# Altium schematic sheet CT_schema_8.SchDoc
size 278 x 170 mm
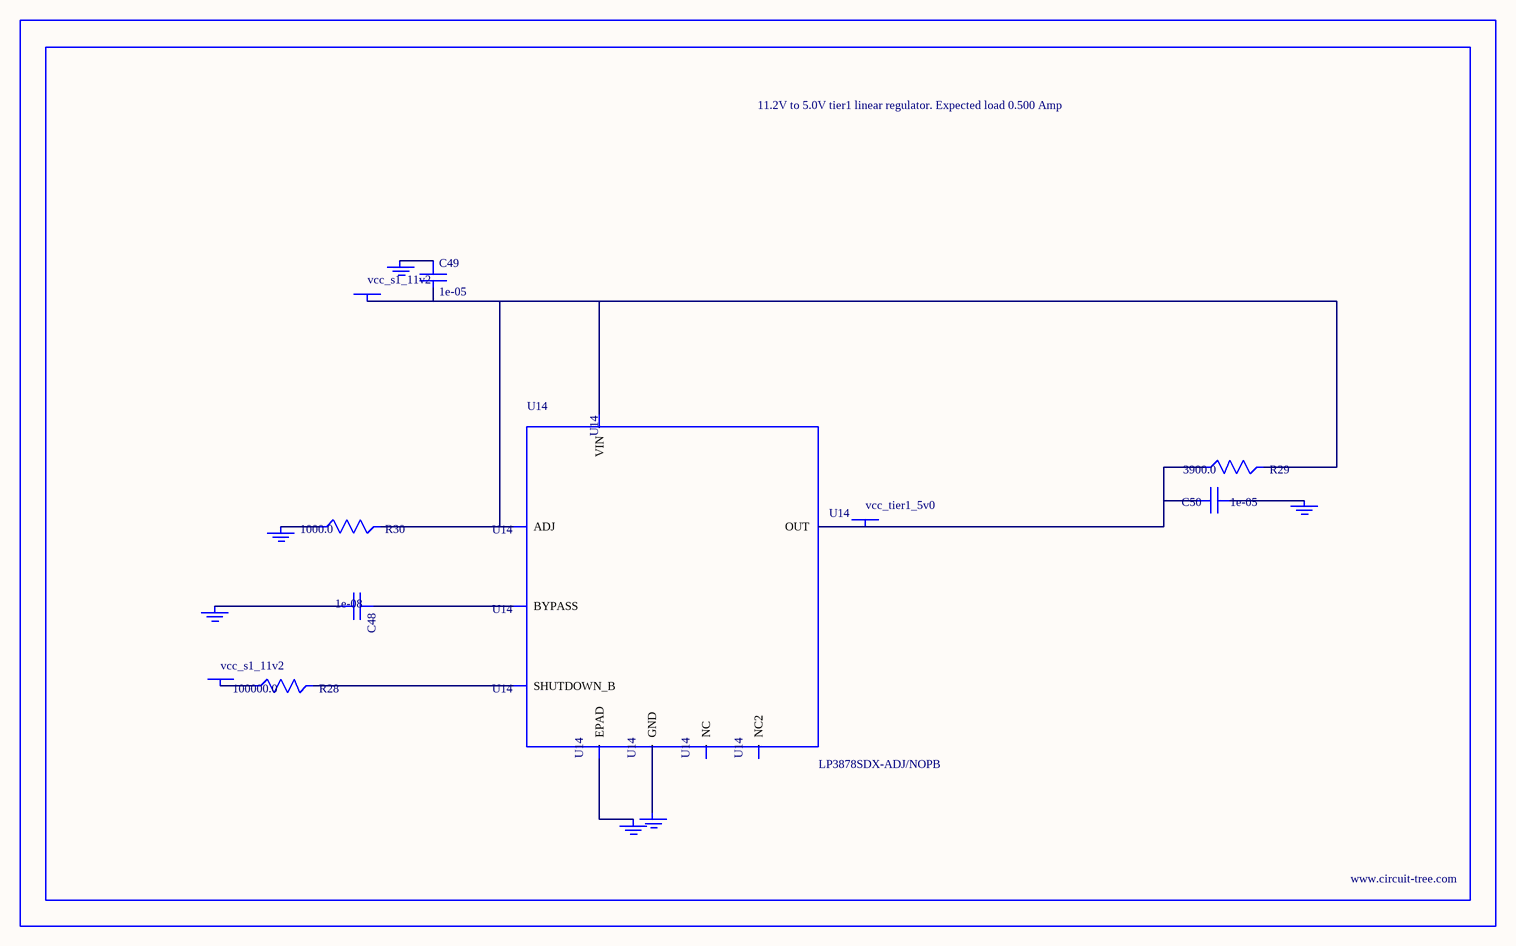
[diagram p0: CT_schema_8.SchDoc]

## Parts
BORDER7  (no value)
C48  1e-08  [C0402]
C49  1e-05  [C1210]
C50  1e-05  [C1210]
GND_INSTANCE_7_0  (no value)
GND_INSTANCE_7_1  (no value)
GND_INSTANCE_7_2  (no value)
GND_INSTANCE_7_3  (no value)
GND_INSTANCE_7_4  (no value)
GND_INSTANCE_7_5  (no value)
POWER_INSTANCE_7_0  vcc_s1_11v2
POWER_INSTANCE_7_1  vcc_s1_11v2
POWER_INSTANCE_7_2  vcc_tier1_5v0
R28  100000.0  [R0603]
R29  3900.0  [R0603]
R30  1000.0  [R0603]
U14  LP3878SDX-ADJ/NOPB  [WSON-8]

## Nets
NetC48_1: C48.1 U14.1(BYPASS)
NetC48_2: C48.2 GND_INSTANCE_7_0.0(GND)
NetC49_1: C49.1 GND_INSTANCE_7_1.0(GND)
NetC49_2: C49.2 POWER_INSTANCE_7_0.0(PWR) R29.2 R30.2 U14.4(VIN) U14.6(ADJ)
NetC50_1: C50.1 GND_INSTANCE_7_2.0(GND)
NetC50_2: C50.2 POWER_INSTANCE_7_2.0(PWR) R29.1 U14.5(OUT)
NetGND_INSTANCE_7_3_0: GND_INSTANCE_7_3.0(GND) R30.1
NetGND_INSTANCE_7_4_0: GND_INSTANCE_7_4.0(GND) U14.PAD(EPAD)
NetGND_INSTANCE_7_5_0: GND_INSTANCE_7_5.0(GND) U14.3(GND)
NetPOWER_INSTANCE_7_1_0: POWER_INSTANCE_7_1.0(PWR) R28.1
NetR28_2: R28.2 U14.8(SHUTDOWN_B)

Not connected (* = marked no-connect by the designer): U14 2(NC) 7(NC2)

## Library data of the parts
BORDER7 = BORDER_PAGE7
C48 = C0402C103K3RAC
C49 = C1210C106K5PACTU
C50 = GRM32DR61E106MA12L
GND_INSTANCE_7_0-GND_INSTANCE_7_5 = GND
POWER_INSTANCE_7_0-POWER_INSTANCE_7_2 = PWR
R28 = RC0603JR-07100KL
R29 = RC0603JR-073K9L
R30 = RC0603JR-071KL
